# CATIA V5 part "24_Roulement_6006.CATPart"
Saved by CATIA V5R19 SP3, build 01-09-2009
Part number: 24_Roulement_6006
Bounding box of the stored display mesh (mm): x 0 to 13, y -27.5 to 27.5, z -27.5 to 27.5
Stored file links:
  C:\Users\Frédéric\Documents\WF\STSCPI 09-11\Projets\Projet multiplicateur eolienne\Maquette eolienne\Standard\24_Roulement_6006.CATPart
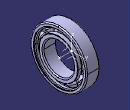
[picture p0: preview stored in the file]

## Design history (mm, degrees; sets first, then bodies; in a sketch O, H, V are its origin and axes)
AxisSystem1: origin (0, 0, 0), X (1, 0, 0), Y (0, 1, 0), Z (0, 0, 1)
Body1 "1" (main body)
  Solid1: solid without history
Body2 "2"
  Solid2: solid without history
Body3 "3"
  Solid3: solid without history
Body4 "4"
  Solid4: solid without history
Body5 "5"
  Solid5: solid without history
Body6 "6"
  Solid6: solid without history
Body7 "7"
  Solid7: solid without history
Body8 "8"
  Solid8: solid without history
Body9 "9"
  Solid9: solid without history
Body10 "10"
  Solid10: solid without history
Body11 "11"
  Solid11: solid without history
Body12 "12"
  Solid12: solid without history
Body13 "13"
  Solid13: solid without history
